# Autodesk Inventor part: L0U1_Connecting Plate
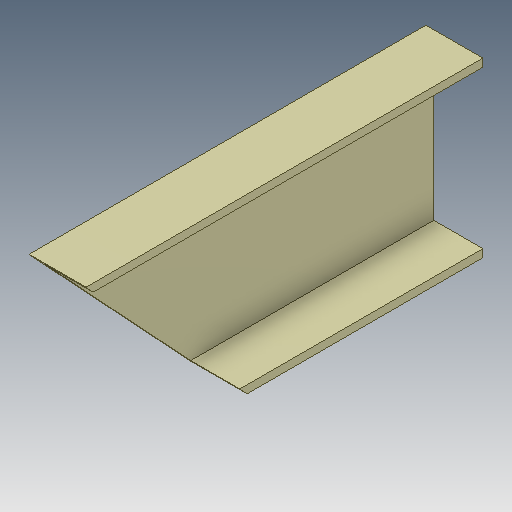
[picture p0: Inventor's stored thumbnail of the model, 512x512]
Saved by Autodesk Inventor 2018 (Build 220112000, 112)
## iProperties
Created: 2018-02
Part Number: L0U1_Connecting Plate
Material: Steel, Mild
Document SubType Name: Modeling
Designer: STK
Density: 7.85 g/cm^3
Appearance: Smooth - Ash
Author: STK
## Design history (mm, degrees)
sketch "Sketch1"
  geometry: L1 (12.7, 127)-(12.7, -127); L2 (0, -139.7)-(0, 139.7); L3 (0, -139.7)-(92.075, -139.7); L4 (92.075, -139.7)-(92.075, -127); L5 (92.075, -127)-(12.7, -127); L6 (0, 139.7)-(92.075, 139.7); L7 (92.075, 139.7)-(92.075, 127); L8 (92.075, 127)-(12.7, 127); L9 (0, 0)-(92.075, 0)
  constraints: 18 end point, 3 horizontal, 3 parallel, 2 perpendicular, 2 vertical alignment, 1 collinear, 1 point on line, 1 vertical, 1 other
  dimensions: "d0" = 279.4 distance of L2.start L2.end; "d1" = 92.075 distance of L2.end L6.end; "d2" = 12.7 distance between parallel lines of L2 L1; "d3" = 12.7 distance between parallel lines of L6 L8
extrude "Extrusion1" new body sketch "Sketch1" distance "d4" = 641.35; taper "d5" = 0 deg
sketch "Sketch2"
  geometry: L1 (-260.35, 0)-(-0.379, 278.525) reference; L2 (0, 0)-(-641.35, 0) reference; L3 (0, 279.4)-(0, 0) reference; L4 (0, 0)-(0, 278.931); L5 (-260.35, 0)-(0, 278.931); L6 (0, 0)-(-260.35, 0); 1 further point
  constraints: 6 end point, 1 collinear, 1 vertical
extrude "Extrusion2" cut sketch "Sketch2" extent not by distance; stored distance "d6" = 508; taper "d7" = 0 deg
body "Solid1"
node "Reference1"
